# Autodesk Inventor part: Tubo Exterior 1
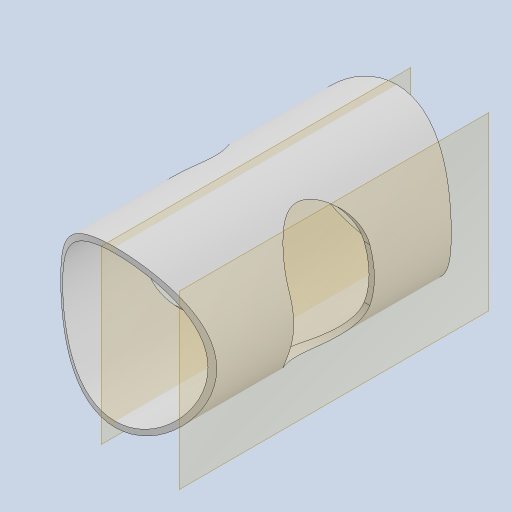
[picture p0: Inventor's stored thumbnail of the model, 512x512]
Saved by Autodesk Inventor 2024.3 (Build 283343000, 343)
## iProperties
Created: 2025-10
Part Number: Tubo Exterior 1
Material: Genérico
Document SubType Name: Modeling
Designer: Asus
Density: 1 g/cm^3
Appearance: Valor por defecto
Author: Asus
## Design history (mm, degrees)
sketch "Boceto1"
  geometry: C1 r 44.45 at (0, 0); C2 r 41.4 at (0, 0); 1 further point
  constraints: 2 centre point, 2 coincident
  dimensions: "d0" = 88.9 diameter of C1; "d1" = 3.05 radial gap between concentric circles of C1 C2
extrude "Extrusión1" new body sketch "Boceto1" stored distance "d2" = 168; taper "d3" = 0 deg
sketch "Boceto4"
  geometry: L1 (44.45, -84)-(44.45, 84) reference; L2 (-44.45, -84)-(44.45, -84) reference; L3 (-44.45, -84)-(-44.45, 84) reference; L4 (-41.4, 84)-(41.4, 84) reference; L5 (44.45, 84)-(-44.45, 84) reference; L6 (44.45, 84)-(44.45, 56.153); L7 (44.45, 84)-(-44.45, 84); L8 (-44.45, 84)-(-44.45, 58.308); L9 (44.45, -84)-(44.45, -61.254); L10 (44.45, -84)-(-44.45, -84); L11 (-44.45, -84)-(-44.45, -62.439); C1 r 80.237 at (0, 0); 5 further points
  constraints: 12 end point, 4 point on line, 2 collinear, 1 centre point, 1 coincident
  dimensions: "d7" = 160.475 diameter of C1
extrude "Extrusión3" cut sketch "Boceto4" extent not by distance; stored distance "d8" = 0; taper "d9" = 0 deg
node "Plano de trabajo1"
sketch "Boceto5"
  geometry: L1 (-15, -23)-(15, -23); L2 (15, -23)-(15, 23); L3 (15, 23)-(-15, 23); L4 (-15, 23)-(-15, -23); L5 (-15, -23)-(15, 23); L6 (15, -23)-(-15, 23); 5 further points
  constraints: 12 end point, 4 midpoint, 2 parallel, 1 horizontal, 1 perpendicular, 6 other
  dimensions: "d10" = 46 distance of L1.end L2.end; "d11" = 30 distance between parallel lines of L4 L2
extrude "Extrusión4" cut sketch "Boceto5" extent not by distance; stored distance "d12" = 0; taper "d13" = 0 deg
node "Sólido1"
